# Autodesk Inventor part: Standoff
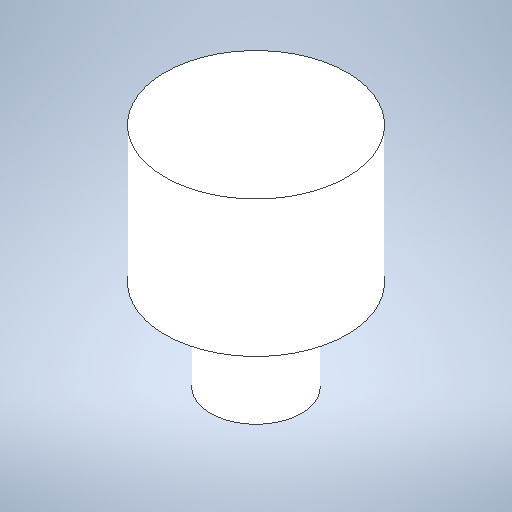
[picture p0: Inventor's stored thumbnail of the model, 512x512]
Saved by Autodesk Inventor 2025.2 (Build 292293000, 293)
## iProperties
Created: 2025-09
Part Number: Standoff
Material: Generic
Document SubType Name: Modeling
Designer: tyler
Density: 1 g/cm^3
Appearance: Default
Author: tyler
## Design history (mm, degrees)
sketch "Sketch1"
  geometry: C1 r 3.175 at (0, 0); 1 further point
  constraints: 1 centre point, 1 coincident
  dimensions: "d0" = 6.35 diameter of C1
extrude "Extrusion1" new body sketch "Sketch1" distance "d1" = 6.35; taper "d2" = 0 deg
sketch "Sketch2"
  geometry: C1 r 6.35 at (0, 0); 1 further point
  constraints: 1 centre point, 1 coincident
  dimensions: "d3" = 12.7 diameter of C1
extrude "Extrusion2" join sketch "Sketch2" distance "d4" = 9.525; taper "d5" = 0 deg
body "Solid1"
